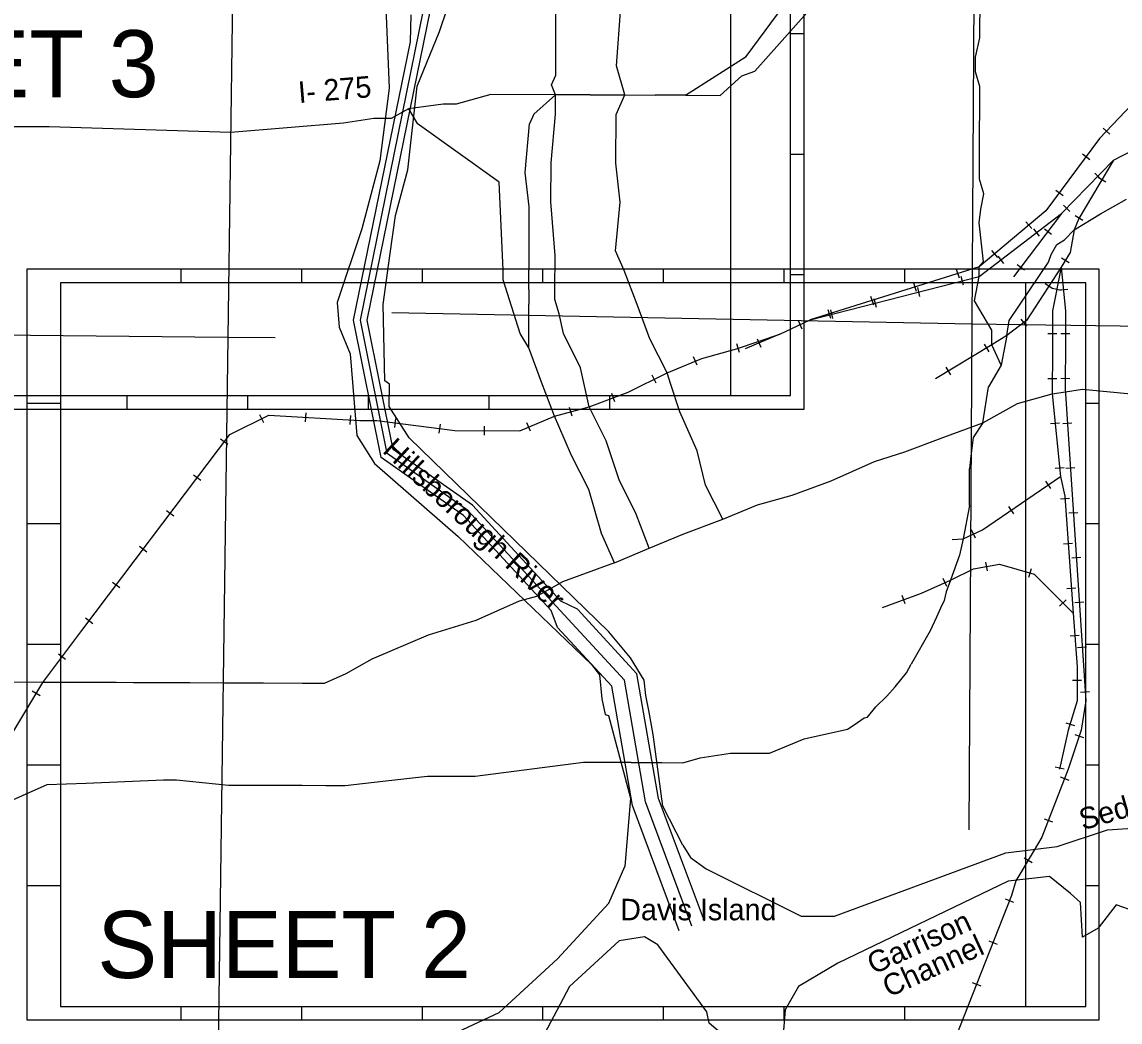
# Model space of a CAD drawing. Extents: x 492225 to 553725, y 1303773 to 1347273.
# Drawn here: x 503393 to 511586, y 1310432 to 1317894 of the extents above; entities that cross this region are included whole.
import ezdxf

# ---------------------------------------------------------------- set-up
doc = ezdxf.new("R2010")
doc.units = 0
for name, color, linetype in [('Level 1', 7, 'Continuous'), ('Level 13', 7, 'Continuous'), ('Level 19', 7, 'Continuous'), ('Level 22', 7, 'Continuous'), ('Level 37', 7, 'Continuous'), ('Level 41', 7, 'Continuous'), ('Level 5', 7, 'Continuous'), ('Level 50', 7, 'Continuous'), ('Level 6', 7, 'Continuous')]:
    doc.layers.add(name, color=color, linetype=linetype)

msp = doc.modelspace()

# ---------------------------------------------------------------- linework, layer by layer
at = {"layer": 'Level 1'}
for p, q in [((505001.79, 1320973.847), (504928.709, 1315540.774)), ((510511.962, 1320917.95), (510479.1, 1315638.587)), ((508678.147, 1320506.301), (508678.147, 1315106.301)), ((509228.147, 1317806.301), (509128.147, 1317806.301)), ((509228.147, 1316906.301), (509128.147, 1316906.301)), ((504580.329, 1315948.53), (504580.329, 1316048.53)), ((505480.329, 1315948.53), (505480.329, 1316048.53)), ((506380.329, 1315948.53), (506380.329, 1316048.53)), ((507280.329, 1315948.53), (507280.329, 1316048.53)), ((508180.329, 1315948.53), (508180.329, 1316048.53)), ((509080.329, 1315948.53), (509080.329, 1316048.53)), ((509228.147, 1316006.301), (509128.147, 1316006.301)), ((509980.329, 1315948.53), (509980.329, 1316048.53)), ((510880.329, 1315948.53), (510880.329, 1310548.53)), ((510479.1, 1315638.587), (506152.448, 1315723.602)), ((510479.1, 1315638.587), (510458.196, 1311867.018)), ((515834.762, 1315574.291), (510479.1, 1315638.587)), ((504928.709, 1315540.774), (499586.966, 1315590.825)), ((504928.709, 1315540.774), (504856.454, 1310168.978)), ((505282.034, 1315537.464), (504928.709, 1315540.774)), ((504178.147, 1315006.301), (504178.147, 1315106.301)), ((505078.147, 1315006.301), (505078.147, 1315106.301)), ((505978.147, 1315006.301), (505978.147, 1315106.301)), ((506878.147, 1315006.301), (506878.147, 1315106.301)), ((507778.147, 1315006.301), (507778.147, 1315106.301)), ((503680.329, 1315048.53), (503430.329, 1315048.53)), ((511430.329, 1315048.53), (511330.329, 1315048.53)), ((503680.329, 1314148.53), (503430.329, 1314148.53)), ((511430.329, 1314148.53), (511330.329, 1314148.53)), ((503680.329, 1313248.53), (503430.329, 1313248.53)), ((511430.329, 1313248.53), (511330.329, 1313248.53)), ((503680.329, 1312348.53), (503430.329, 1312348.53)), ((511430.329, 1312348.53), (511330.329, 1312348.53)), ((503680.329, 1311448.53), (503430.329, 1311448.53)), ((511430.329, 1311448.53), (511330.329, 1311448.53)), ((504580.329, 1310448.53), (504580.329, 1310548.53)), ((505480.329, 1310448.53), (505480.329, 1310548.53)), ((506380.329, 1310448.53), (506380.329, 1310548.53)), ((507280.329, 1310448.53), (507280.329, 1310548.53)), ((508180.329, 1310448.53), (508180.329, 1310548.53)), ((509080.329, 1310448.53), (509080.329, 1310548.53)), ((509980.329, 1310448.53), (509980.329, 1310548.53))]:
    msp.add_line(p, q, dxfattribs=at)
for points in [[(501228.147, 1315006.301), (509228.147, 1315006.301), (509228.147, 1320606.301), (501228.147, 1320606.301)], [(501478.147, 1315106.301), (509128.147, 1315106.301), (509128.147, 1320506.301), (501478.147, 1320506.301)], [(503430.329, 1310448.53), (511430.329, 1310448.53), (511430.329, 1316048.53), (503430.329, 1316048.53)], [(503680.329, 1310548.53), (511330.329, 1310548.53), (511330.329, 1315948.53), (503680.329, 1315948.53)]]:
    msp.add_lwpolyline(points, close=True, dxfattribs=at)
at = {"layer": 'Level 13'}
for p, q in [((508796.428, 1317636.777), (509250.688, 1318253.13)), ((507375.852, 1317605.741), (507377.223, 1317969.292)), ((507827.674, 1317567.688), (507861.596, 1318003.828)), ((508860.586, 1317527.471), (509249.605, 1317962.29)), ((507375.44, 1317496.677), (507375.852, 1317605.741)), ((507891.419, 1317349.316), (507827.674, 1317567.688)), ((508343.38, 1317347.624), (508796.428, 1317636.777)), ((507342.883, 1317424.088), (507375.44, 1317496.677)), ((508763.603, 1317491.477), (508860.586, 1317527.471)), ((507374.891, 1317351.256), (507342.883, 1317424.088)), ((506890.648, 1317353.081), (506632.108, 1317281.347)), ((507374.891, 1317351.256), (506890.648, 1317353.081)), ((507374.344, 1317205.836), (507374.891, 1317351.256)), ((507633.155, 1317350.285), (507891.419, 1317349.316)), ((507826.307, 1317204.138), (507891.419, 1317349.316)), ((507891.419, 1317349.316), (508117.399, 1317348.469)), ((508343.38, 1317347.624), (508117.399, 1317348.469)), ((506276.857, 1317246.336), (506147.449, 1317174.116)), ((506535.259, 1317281.713), (506276.857, 1317246.336)), ((506632.108, 1317281.347), (506535.259, 1317281.713)), ((506018.315, 1317174.607), (505792.195, 1317139.11)), ((506147.449, 1317174.116), (506018.315, 1317174.607)), ((507340.689, 1316842.407), (507374.344, 1317205.836)), ((507824.939, 1316840.588), (507826.307, 1317204.138)), ((503596.799, 1317111.164), (502240.905, 1317116.419)), ((504952.554, 1317069.6), (503596.799, 1317111.164)), ((505792.195, 1317139.11), (504952.554, 1317069.6)), ((507339.592, 1316551.567), (507340.689, 1316842.407)), ((507856.13, 1316549.627), (507824.939, 1316840.588)), ((507370.368, 1316151.54), (507339.592, 1316551.567)), ((507822.479, 1316186.197), (507856.13, 1316549.627)), ((507886.501, 1316040.534), (507822.479, 1316186.197)), ((507369.408, 1315897.054), (507370.368, 1316151.54)), ((507982.398, 1315785.687), (507886.501, 1316040.534)), ((507369.134, 1315824.345), (507369.408, 1315897.054)), ((507401.007, 1315715.158), (507369.134, 1315824.345)), ((508078.295, 1315530.839), (507982.398, 1315785.687)), ((507432.744, 1315569.617), (507401.007, 1315715.158)), ((507560.923, 1315314.647), (507432.744, 1315569.617)), ((508206.479, 1315275.87), (508078.295, 1315530.839)), ((507624.397, 1315023.563), (507560.923, 1315314.647)), ((508235.207, 1315188.146), (508206.479, 1315275.87)), ((508302.243, 1314984.668), (508235.207, 1315188.146)), ((507650.355, 1314972.205), (507624.397, 1315023.563)), ((507752.579, 1314768.594), (507650.355, 1314972.205)), ((508430.294, 1314693.346), (508302.243, 1314984.668)), ((507848.342, 1314477.391), (507752.579, 1314768.594)), ((508493.912, 1314438.619), (508430.294, 1314693.346)), ((507976.528, 1314222.422), (507848.342, 1314477.391)), ((508622.102, 1314183.653), (508493.912, 1314438.619)), ((508072.429, 1313967.574), (507976.528, 1314222.422))]:
    msp.add_line(p, q, dxfattribs=at)
for points in [[(508343.38, 1317347.624), (508601.644, 1317346.659), (508763.603, 1317491.477)], [(507633.155, 1317350.285), (507522.254, 1317351.258), (507374.891, 1317351.256)]]:
    msp.add_lwpolyline(points, dxfattribs=at)
at = {"layer": 'Level 22'}
for p, q in [((510540.231, 1317775.738), (510541.439, 1318102.933)), ((510507.411, 1317630.437), (510540.231, 1317775.738)), ((510507.009, 1317521.372), (510507.411, 1317630.437)), ((510538.889, 1317412.188), (510507.009, 1317521.372)), ((510538.353, 1317266.768), (510538.889, 1317412.188)), ((507212.929, 1317206.443), (507374.891, 1317351.256)), ((506276.857, 1317246.336), (506341.009, 1317137.026)), ((510537.547, 1317048.638), (510538.353, 1317266.768)), ((507212.929, 1317206.443), (507180.37, 1317133.854)), ((506952.739, 1316698.446), (506341.009, 1317137.026)), ((507146.714, 1316770.426), (507180.37, 1317133.854)), ((507178.037, 1316515.819), (507146.714, 1316770.426)), ((506982.548, 1316043.934), (506952.739, 1316698.446)), ((510547.135, 1316497.453), (510568.22, 1316612.258)), ((507176.802, 1316188.624), (507178.037, 1316515.819)), ((510535.132, 1316394.248), (510547.135, 1316497.453)), ((511439.343, 1316463.639), (511633.444, 1316571.996)), ((511243.906, 1316343.655), (511439.343, 1316463.639)), ((510566.343, 1316103.289), (510535.132, 1316394.248)), ((507175.703, 1315897.784), (507176.802, 1316188.624)), ((510533.925, 1316067.053), (510566.343, 1316103.289)), ((510758.439, 1315666.317), (511050.602, 1316101.509)), ((506982.273, 1315971.224), (506982.548, 1316043.934)), ((510533.656, 1315994.343), (510533.925, 1316067.053)), ((507109.899, 1315570.833), (506982.273, 1315971.224)), ((510500.701, 1315812.687), (510533.656, 1315994.343)), ((507175.703, 1315897.784), (507175.291, 1315788.719)), ((507174.056, 1315461.524), (507175.291, 1315788.719)), ((510628.631, 1315485.016), (510629.034, 1315594.082)), ((510739.947, 1315554.409), (510758.439, 1315666.317)), ((507174.056, 1315461.524), (507109.899, 1315570.833)), ((510739.947, 1315554.409), (510697.808, 1315333.523)), ((507269.949, 1315206.674), (507174.056, 1315461.524)), ((510697.808, 1315333.523), (510628.631, 1315485.016)), ((510697.808, 1315333.523), (510604.228, 1315170.994)), ((507365.844, 1314951.824), (507269.949, 1315206.674)), ((510561.916, 1314903.574), (510604.228, 1315170.994)), ((510820.731, 1315048.044), (511079.277, 1315119.806)), ((511079.277, 1315119.806), (511177.766, 1315133.526)), ((511177.766, 1315133.526), (511305.404, 1315155.333)), ((511305.404, 1315155.333), (511692.687, 1315117.561)), ((510561.916, 1314903.574), (510820.731, 1315048.044)), ((507397.854, 1314878.993), (507365.844, 1314951.824)), ((507493.888, 1314660.499), (507397.854, 1314878.993)), ((510270.949, 1314795.58), (510561.916, 1314903.574)), ((509979.979, 1314687.588), (510270.949, 1314795.58)), ((507622.071, 1314405.529), (507493.888, 1314660.499)), ((509430.322, 1314471.491), (509753.714, 1314615.713)), ((509753.714, 1314615.713), (509979.979, 1314687.588)), ((510462.78, 1314285.897), (510462.504, 1314560.744)), ((509139.348, 1314363.504), (509430.322, 1314471.491)), ((507717.696, 1314077.97), (507622.071, 1314405.529)), ((508622.102, 1314183.653), (508880.794, 1314291.755)), ((508880.794, 1314291.755), (509139.348, 1314363.504)), ((510462.78, 1314285.897), (510414.079, 1314037.404)), ((508331.124, 1314075.673), (508622.102, 1314183.653)), ((507813.734, 1313859.477), (507717.696, 1314077.97)), ((508072.429, 1313967.574), (508331.124, 1314075.673)), ((510414.079, 1314037.404), (510387.8, 1313915.347)), ((507813.734, 1313859.477), (508072.429, 1313967.574)), ((510387.8, 1313915.347), (510319.957, 1313729.457)), ((507813.734, 1313859.477), (507425.755, 1313715.512)), ((507425.755, 1313715.512), (507361.047, 1313679.4)), ((507361.047, 1313679.4), (507231.629, 1313607.176)), ((507102.347, 1313571.308), (506778.936, 1313427.106)), ((507231.629, 1313607.176), (507102.347, 1313571.308)), ((506778.936, 1313427.106), (506423.374, 1313319.383)), ((510215.618, 1313453.472), (510168.753, 1313351.918)), ((506423.374, 1313319.383), (506002.961, 1313139.199)), ((510168.753, 1313351.918), (510028.35, 1313102.311)), ((506002.961, 1313139.199), (505808.828, 1313030.87)), ((505808.828, 1313030.87), (505647.118, 1312958.774)), ((503548.489, 1312966.815), (503193.337, 1312968.187)), ((503839.069, 1312965.696), (503548.489, 1312966.815)), ((503903.642, 1312965.446), (503839.069, 1312965.696)), ((504097.362, 1312964.702), (503903.642, 1312965.446)), ((504226.508, 1312964.205), (504097.362, 1312964.702)), ((504387.941, 1312963.585), (504226.508, 1312964.205)), ((504549.374, 1312962.967), (504387.941, 1312963.585)), ((504646.234, 1312962.595), (504549.374, 1312962.967)), ((504904.526, 1312961.607), (504646.234, 1312962.595)), ((505195.105, 1312960.497), (504904.526, 1312961.607)), ((505485.685, 1312959.388), (505195.105, 1312960.497)), ((505647.118, 1312958.774), (505485.685, 1312959.388)), ((509229.438, 1312545.396), (509552.576, 1312616.908)), ((508970.736, 1312437.292), (509229.438, 1312545.396)), ((508324.724, 1312366.989), (508454.008, 1312402.862)), ((508454.008, 1312402.862), (508680.153, 1312438.373)), ((508680.153, 1312438.373), (508970.736, 1312437.292)), ((507582.122, 1312369.772), (506774.534, 1312263.747)), ((507937.28, 1312368.439), (507582.122, 1312369.772)), ((507937.28, 1312368.439), (508060.62, 1312369.068)), ((508060.62, 1312369.068), (508131.002, 1312367.713)), ((508131.002, 1312367.713), (508165.872, 1312367.583)), ((508165.872, 1312367.583), (508324.724, 1312366.989)), ((504449.72, 1312236.238), (503872.324, 1312212.28)), ((504546.581, 1312235.866), (504449.72, 1312236.238)), ((504933.889, 1312198.029), (504546.581, 1312235.866)), ((506419.375, 1312265.089), (506086.344, 1312226.723)), ((506774.534, 1312263.747), (506419.375, 1312265.089)), ((503577.825, 1312203.236), (502930.952, 1311914.892)), ((503872.324, 1312212.28), (503577.825, 1312203.236)), ((505192.185, 1312197.043), (504933.889, 1312198.029)), ((505482.77, 1312195.934), (505192.185, 1312197.043)), ((505661.319, 1312195.254), (505482.77, 1312195.934)), ((505805.643, 1312194.706), (505661.319, 1312195.254)), ((506086.344, 1312226.723), (505805.643, 1312194.706))]:
    msp.add_line(p, q, dxfattribs=at)
for points in [[(510568.22, 1316612.258), (510536.339, 1316721.443), (510537.547, 1317048.638)], [(511050.602, 1316101.509), (511072.764, 1316158.143), (511114.364, 1316233.609), (511171.313, 1316268.302), (511243.906, 1316343.655)], [(510629.034, 1315594.082), (510564.867, 1315703.384), (510500.701, 1315812.687)], [(510561.916, 1314903.574), (510489.189, 1314793.322), (510473.179, 1314653.775), (510462.504, 1314560.744)], [(510319.957, 1313729.457), (510288.641, 1313642.319), (510272.907, 1313578.392), (510247.007, 1313521.489), (510215.618, 1313453.472)], [(509763.707, 1312783.362), (509846.662, 1312864.491), (509908.911, 1312934.063), (509950.432, 1312986.262), (509991.952, 1313038.46), (510028.35, 1313102.311)], [(509552.576, 1312616.908), (509603.068, 1312650.168), (509675.584, 1312702.251), (509701.435, 1312707.972), (509763.707, 1312783.362)]]:
    msp.add_lwpolyline(points, dxfattribs=at)
at = {"layer": 'Level 37'}
for p, q in [((511830.337, 1317443.808), (511432.356, 1317023.539)), ((511460.524, 1317102.253), (511509.419, 1317055.949)), ((511305.631, 1316909.056), (511359.739, 1316868.967)), ((511537.659, 1316863.189), (511148.79, 1316464.704)), ((511396.628, 1316766.879), (511444.823, 1316719.848)), ((511422.929, 1316736.688), (511480.75, 1316702.17)), ((511106.289, 1316640.001), (511160.397, 1316599.912)), ((511162.759, 1316527.227), (511210.954, 1316480.194)), ((511148.79, 1316464.704), (510791.928, 1315993.393)), ((511251.288, 1316449.168), (511309.109, 1316414.65)), ((510883.926, 1316403.583), (510927.121, 1316351.92)), ((510983.694, 1316296.078), (510942.791, 1316349.573)), ((511020.879, 1316351.548), (511074.566, 1316310.897)), ((510627.035, 1316188.793), (510670.23, 1316137.13)), ((510717.693, 1316092.679), (510676.789, 1316146.174)), ((511149.325, 1316133.844), (511207.145, 1316099.325)), ((510533.925, 1316067.053), (509273.36, 1315671.804)), ((510364.094, 1316049.089), (510384.24, 1315984.833)), ((510818.742, 1316084.585), (510872.429, 1316043.933)), ((511147.32, 1316064.799), (511178.402, 1315737.485)), ((510044.578, 1315948.906), (510064.725, 1315884.649)), ((510417.102, 1315929.758), (510400.407, 1315994.997)), ((511027.752, 1315942.858), (511084.186, 1315906.117)), ((509725.063, 1315848.722), (509745.209, 1315784.464)), ((510092.704, 1315846.737), (510076.009, 1315911.976)), ((511081.292, 1315907.299), (511147.311, 1315894.019)), ((511129.628, 1315894.938), (511196.668, 1315901.304)), ((509768.306, 1315763.716), (509751.61, 1315828.956)), ((509405.547, 1315748.538), (509425.694, 1315684.281)), ((509443.907, 1315680.695), (509427.212, 1315745.934)), ((510846.361, 1315676.918), (510886.931, 1315623.169)), ((509046.964, 1315563.579), (509273.36, 1315671.804)), ((509183.497, 1315666.167), (509212.54, 1315605.41)), ((509046.964, 1315563.579), (508788.281, 1315455.476)), ((508879.501, 1315530.089), (508905.466, 1315467.954)), ((511047.258, 1315569.19), (511114.599, 1315568.943)), ((511144.117, 1315570.182), (511211.457, 1315569.935)), ((508747.61, 1315428.194), (508726.295, 1315492.074)), ((510572.767, 1315490.713), (510607.469, 1315433.002)), ((508429.634, 1315332.63), (508403.67, 1315394.765)), ((510285.798, 1315318.153), (510320.5, 1315260.442)), ((508125.509, 1315198.144), (508095.597, 1315258.478)), ((511046.027, 1315234.337), (511113.369, 1315234.09)), ((511142.886, 1315235.329), (511210.227, 1315235.083)), ((507817.395, 1315059.267), (507793.968, 1315122.402)), ((505197.376, 1314903.648), (505167.469, 1314963.984)), ((505508.78, 1314910.448), (505512.643, 1314977.679)), ((505843.081, 1314891.245), (505846.944, 1314958.476)), ((507497.06, 1314953.289), (507479.056, 1315018.179)), ((506174.314, 1314869.46), (506182.929, 1314936.248)), ((506506.415, 1314826.63), (506515.029, 1314893.418)), ((506844.518, 1314811.053), (506844.772, 1314878.394)), ((507186.884, 1314840.556), (507160.922, 1314902.692)), ((511067.877, 1314897.093), (511134.879, 1314903.845)), ((511159.412, 1314898.693), (511226.609, 1314903.108)), ((504929.435, 1314740.506), (504875.684, 1314781.073)), ((511101.448, 1314563.925), (511168.449, 1314570.678)), ((511181.362, 1314564.558), (511248.558, 1314568.973)), ((504727.715, 1314473.229), (504673.964, 1314513.796)), ((511070.344, 1314412.132), (511032.374, 1314467.748)), ((511141.034, 1314335.213), (511208.209, 1314339.938)), ((504525.996, 1314205.951), (504472.245, 1314246.518)), ((510793.795, 1314223.322), (510755.825, 1314278.938)), ((511203.312, 1314230.423), (511270.509, 1314234.838)), ((510506.161, 1314042.545), (510478.119, 1314103.77)), ((504324.332, 1313938.628), (504270.584, 1313979.198)), ((511164.521, 1314001.183), (511231.697, 1314005.907)), ((511225.262, 1313896.288), (511292.459, 1313900.703)), ((510596.548, 1313797.908), (510584.371, 1313864.139)), ((510905.361, 1313751.499), (510923.847, 1313816.254)), ((504122.597, 1313671.362), (504068.849, 1313711.932)), ((510294.041, 1313680.87), (510266.405, 1313742.28)), ((511188.009, 1313667.153), (511255.183, 1313671.877)), ((509982.921, 1313551.513), (509959.49, 1313614.648)), ((511134.681, 1313536.267), (511182.495, 1313583.688)), ((511247.213, 1313562.153), (511314.409, 1313566.568)), ((503920.863, 1313404.095), (503867.114, 1313444.665)), ((511213.983, 1313313.722), (511281.125, 1313318.894)), ((511269.162, 1313228.018), (511336.359, 1313232.433)), ((503719.083, 1313136.853), (503665.343, 1313177.435)), ((511231.47, 1312982.268), (511298.811, 1312982.021)), ((503527.986, 1312866.825), (503470.173, 1312901.358)), ((511291.113, 1312893.883), (511358.309, 1312898.298)), ((511180.185, 1312664.619), (511244.685, 1312645.267)), ((511249.269, 1312577.076), (511313.08, 1312555.563)), ((511102.727, 1312336.545), (511168.412, 1312321.708)), ((511139.805, 1312262.175), (511202.654, 1312237.99)), ((511019.54, 1311949.662), (511082.389, 1311925.476)), ((510871.088, 1311657.253), (510928.908, 1311622.731)), ((510728.607, 1311350.602), (510791.263, 1311325.923)), ((510605.888, 1311039.043), (510668.543, 1311014.364)), ((510483.167, 1310727.486), (510545.823, 1310702.807))]:
    msp.add_line(p, q, dxfattribs=at)
for points in [[(511537.659, 1316863.189), (511908.006, 1317054.158), (511999.714, 1317060.003), (512212.511, 1317073.408), (512345.649, 1317108.914), (512369.562, 1317115.372), (512410.228, 1317112.315)], [(511432.356, 1317023.539), (511032.638, 1316484.034), (510533.925, 1316067.053)], [(511537.659, 1316863.189), (511277.79, 1316427.875), (511243.906, 1316343.655), (511212.289, 1316173.628), (511147.32, 1316064.799)], [(509273.36, 1315671.804), (510533.656, 1315994.343), (511148.79, 1316464.704)], [(511147.32, 1316064.799), (510887.576, 1315665.842), (510739.947, 1315554.409), (510628.631, 1315485.016), (510207.993, 1315232.078)], [(511147.32, 1316064.799), (511081.549, 1315737.841), (511080.499, 1315452.453), (511079.277, 1315119.806), (511141.575, 1314501.534)], [(511178.402, 1315737.485), (511177.601, 1315519.356), (511176.264, 1315155.806), (511329.151, 1312828.497), (511296.064, 1312610.486), (511198.135, 1312320.001), (511002.542, 1311811.742), (510937.566, 1311702.914), (510807.613, 1311485.259), (510774.923, 1311376.313), (510063.387, 1309569.888), (509960.055, 1309307.057), (510520.7205, 1307817.676)], [(503273.558, 1312506.525), (503548.489, 1312966.815), (503840.565, 1313353.603), (504337.733, 1314012.272), (504359.8, 1314041.635), (504943.917, 1314815.588), (505235.039, 1314959.898), (505912.884, 1314920.962), (506042.024, 1314920.472), (506332.45, 1314883.015), (506622.878, 1314845.56), (507107.153, 1314843.733), (507365.844, 1314951.824), (507624.397, 1315023.563), (507915.37, 1315131.538), (508206.479, 1315275.87), (508465.164, 1315383.97), (508723.712, 1315455.716), (509046.964, 1315563.579)], [(510332.699, 1314031.888), (510414.079, 1314037.404), (510558.965, 1314103.765), (511141.575, 1314501.534)], [(511141.575, 1314501.534), (511173.326, 1314355.997), (511234.694, 1313483.241)], [(509814.24, 1313524.826), (510105.219, 1313632.817), (510319.957, 1313729.457), (510493.321, 1313813.163), (510687.169, 1313848.805), (510945.189, 1313775.146), (511234.694, 1313483.241)], [(511234.694, 1313483.241), (511265.511, 1313083.218), (511264.578, 1312828.733), (511199.204, 1312610.841), (511133.562, 1312320.238)]]:
    msp.add_lwpolyline(points, dxfattribs=at)
at = {"layer": 'Level 5'}
for points in [[(506109.189, 1317999.758), (506132.38, 1317399.596), (506064.092, 1316858.083), (505929.223, 1316350.079), (505744.224, 1315800.585), (505760.334, 1315617.155), (505843.084, 1315416.885), (505891.275, 1314808.333), (506024.005, 1314599.583), (506647.444, 1314056.017), (507642.53, 1313099.938), (507702.714, 1313024.093), (507718.922, 1312844.343), (507743.602, 1312727.562), (507768.572, 1312719.173), (507933.392, 1312101.932), (507890.204, 1311593.658)], [(508324.051, 1311750.713), (508174.921, 1312042.873), (508101.511, 1312576.475), (508071.366, 1312743.375), (508047.299, 1312868.455), (508036.359, 1312983.747), (507933.526, 1313150.34), (507770.451, 1313344.245), (506282.914, 1314790.507), (506133.604, 1315024.326), (506134.114, 1315190.987), (506100.834, 1315216.117), (506088.599, 1315786.034), (506136.963, 1316149.451), (506179.532, 1316449.353), (506272.251, 1316790.785), (506340.769, 1317415.648), (506508.689, 1317823.542), (506567.558, 1317998.363)], [(508324.051, 1311750.713), (508382.121, 1311658.884), (508498.541, 1311575.174), (509205.919, 1311223.01), (509455.928, 1311222.273), (510732.503, 1311693.517), (511116.011, 1311742.371), (511491.429, 1311866.265), (511716.499, 1311882.288), (512475.665, 1312130.036), (512650.934, 1312212.848), (512843.374, 1312462.331), (512852.213, 1312628.962)], [(503080.1103, 1307817.676), (503387.645, 1308123.38), (503713.204, 1308297.424), (504555.42, 1308453.263), (504955.869, 1308585.398), (505197.988, 1308726.38), (505399.156, 1309109.154), (505642.764, 1309750.149), (505910.283, 1310016.063), (506953.509, 1310504.655), (507388.096, 1310903.421), (507772.714, 1311318.997), (507890.204, 1311593.658)], [(511697.949, 1311257.264), (511556.44, 1311307.693), (511422.551, 1311133.081), (511305.692, 1311066.72), (511289.791, 1311325.161), (511214.991, 1311392.05), (511059.932, 1311518.059), (510749.703, 1311483.335), (509479.889, 1310872.151), (509187.67, 1310698.018), (509087.15, 1310523.276), (509069.821, 1310306.664), (509442.531, 1309530.435), (509467.471, 1309513.715), (509682.451, 1308937.984), (509682.451, 1308937.984), (509831.731, 1308687.505), (509947.341, 1308337.114), (509938.921, 1308303.804), (510167.4157, 1307817.676)], [(509743.2599, 1307817.676), (509737.633, 1307887.69), (509472.563, 1308421.89), (509431.373, 1308580.371), (509273.873, 1308872.53), (509257.413, 1308939.27), (509215.833, 1308964.39), (509124.983, 1309248.041), (508976.003, 1309590.181), (508851.543, 1309782.23), (508793.833, 1309982.441), (508586.623, 1310366.43), (508520.123, 1310424.99), (508503.693, 1310508.36), (508138.484, 1311009.518), (508038.644, 1311068.158), (507849.757, 1311039.237), (507478.559, 1310696.866), (507244.448, 1310253.757)]]:
    msp.add_lwpolyline(points, dxfattribs=at)
at = {"layer": 'Level 50'}
for p, q in [((505969.074, 1315668.009), (506442.022, 1317985.784)), ((506291.259, 1317747.1), (506296.126, 1317948.234)), ((505867.05, 1315668.183), (506291.259, 1317747.1)), ((506072.121, 1314645.092), (505867.05, 1315668.183)), ((506162.323, 1314703.9), (505969.074, 1315668.009)), ((506753.462, 1314287.995), (506162.323, 1314703.9)), ((506687.182, 1314212.357), (506072.121, 1314645.092)), ((507414.048, 1313571.43), (506753.462, 1314287.995)), ((507340.524, 1313503.65), (506687.182, 1314212.357)), ((507536.856, 1313511.981), (507414.048, 1313571.43)), ((507389.808, 1313376.421), (507340.524, 1313503.65)), ((507981.754, 1313029.381), (507536.856, 1313511.981)), ((507794.67, 1312937.251), (507389.808, 1313376.421)), ((508141.54, 1312100.771), (507981.754, 1313029.381)), ((507947.624, 1312048.341), (507794.67, 1312937.251)), ((508484.225, 1311183.782), (508141.54, 1312100.771)), ((508296.879, 1311113.77), (507947.624, 1312048.341))]:
    msp.add_line(p, q, dxfattribs=at)
at = {"layer": 'Level 6'}
for p, q in [((505918.062, 1315668.096), (506390.232, 1317982.056)), ((506117.222, 1314674.496), (505918.062, 1315668.096)), ((506720.322, 1314250.176), (506117.222, 1314674.496)), ((507888.212, 1312983.316), (506720.322, 1314250.176)), ((508044.582, 1312074.556), (507888.212, 1312983.316)), ((508390.552, 1311148.776), (508044.582, 1312074.556))]:
    msp.add_line(p, q, dxfattribs=at)

# ---------------------------------------------------------------- texts
at = {"layer": 'Level 1'}
for s, p in [('SHEET 3', (501626.284, 1317332.615)), ('SHEET 2', (503955.869, 1310760.471))]:
    msp.add_text(s, height=500, dxfattribs=at).set_placement(p)
at = {"layer": 'Level 19'}
msp.add_text('I- 275', height=160, rotation=4.73179443, dxfattribs=at).set_placement((505460.494, 1317288.494))
at = {"layer": 'Level 41'}
for s, height, rotation, p in [('Hillsborough River', 159.999996, 316.97929444, (506074.979, 1314687.196)), ('Seddon Island', 159.999996, 16.37247494, (511308.194, 1311862.077)), ('Garrison', 160, 24.55639995, (509745.795, 1310784.487)), ('Channel', 160, 24.55639995, (509860.369, 1310613.448))]:
    msp.add_text(s, height=height, rotation=rotation, dxfattribs=at).set_placement(p)
msp.add_text('Davis Island', height=159.999996, dxfattribs=at).set_placement((507856.627, 1311191.619))

doc.saveas('drawing.dxf')
